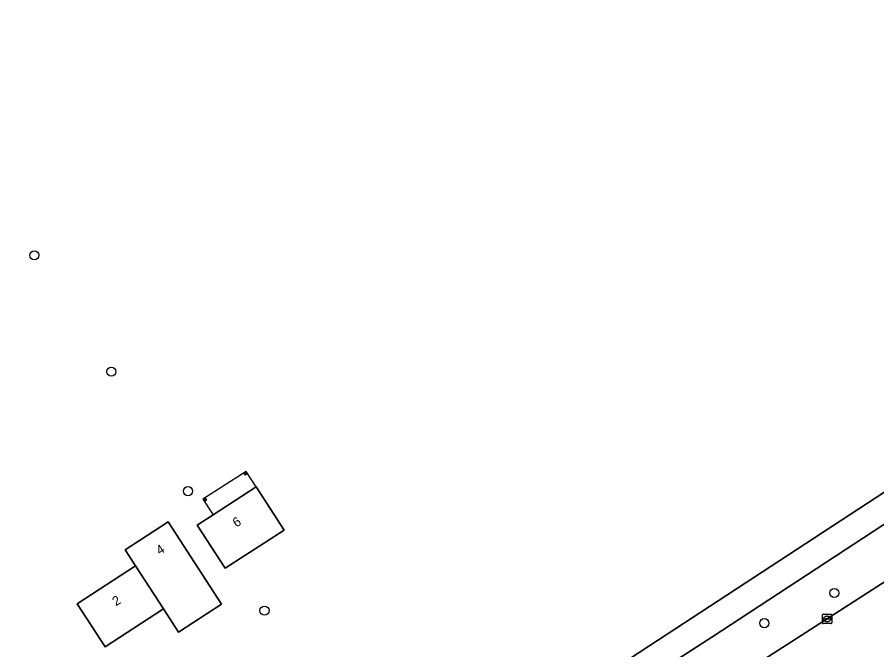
# Model space of a CAD drawing. Extents: x 159451 to 160664, y 388402 to 389723.
# Drawn here: x 159684.1 to 159776, y 389199.6 to 389267.3 of the extents above; entities that cross this region are included whole.
import ezdxf

# ---------------------------------------------------------------- set-up
doc = ezdxf.new("R2010")
doc.units = 0
for name, color, linetype in [('IMGEO_Berm_groen', 7, 'Continuous'), ('IMGEO_Boom', 7, 'Continuous'), ('IMGEO_Fietspad_gesloten', 7, 'Continuous'), ('IMGEO_Groenvoorziening', 7, 'Continuous'), ('IMGEO_Kolk', 7, 'Continuous'), ('IMGEO_Pand', 7, 'Continuous'), ('IMGEO_Pand_nummerreeks', 7, 'Continuous'), ('IMGEO_Pand_overbouw', 7, 'Continuous'), ('IMGEO_Rijbaan_lokaal_gesloten', 7, 'Continuous')]:
    doc.layers.add(name, color=color, linetype=linetype)

msp = doc.modelspace()

# ---------------------------------------------------------------- linework, layer by layer
at = {"layer": 'IMGEO_Berm_groen'}
msp.add_lwpolyline([(159781.643, 389216.263), (159758.299, 389200.996), (159737.096, 389187.355), (159738.318, 389185.435), (159741.003, 389183.824), (159754.281, 389192.419), (159786.052, 389212.871)], dxfattribs=at)
at = {"layer": 'IMGEO_Boom'}
for centre in [(159685.893, 389241.819), (159694.126, 389229.381), (159702.309, 389216.594), (159771.412, 389205.703), (159710.493, 389203.831), (159763.933, 389202.482)]:
    msp.add_circle(centre, 0.489, dxfattribs=at)
at = {"layer": 'IMGEO_Fietspad_gesloten'}
for points in [[(159683.696, 389152.464), (159687.097, 389154.672), (159691.96, 389158.015), (159702.684, 389165.018), (159709.597, 389169.401), (159714.574, 389172.778), (159719.558, 389176.127), (159726.565, 389180.529), (159731.823, 389183.917), (159737.096, 389187.355), (159758.299, 389200.996), (159781.643, 389216.263), (159789.265, 389221.193), (159827.078, 389245.82), (159832.314, 389249.122), (159833.66, 389250), (159874.622, 389276.708)], [(159858.151, 389269.353), (159792.67, 389226.891), (159787.277, 389223.364), (159784.328, 389221.435), (159717.814, 389177.926), (159716.666, 389177.127), (159711.829, 389174.024), (159709.019, 389172.233), (159708.905, 389172.147), (159708.794, 389172.235), (159699.251, 389166.039), (159696.145, 389164.01), (159691.273, 389160.827), (159687.914, 389158.632), (159677.234, 389152.002)]]:
    msp.add_lwpolyline(points, dxfattribs=at)
at = {"layer": 'IMGEO_Groenvoorziening'}
msp.add_lwpolyline([(159691.581, 389172.29), (159696.145, 389164.01), (159699.251, 389166.039), (159708.794, 389172.235), (159708.905, 389172.147), (159709.019, 389172.233), (159711.829, 389174.024), (159716.666, 389177.127), (159717.814, 389177.926), (159784.328, 389221.435), (159782.969, 389223.526), (159785.892, 389225.495), (159787.277, 389223.364), (159792.67, 389226.891), (159858.151, 389269.353)], dxfattribs=at)
for points in [[(159708.497, 389218.649), (159708.617, 389218.464), (159708.432, 389218.345), (159708.313, 389218.529)], [(159709.602, 389217.049), (159712.584, 389212.435), (159706.305, 389208.362), (159703.303, 389212.96), (159704.993, 389214.057)], [(159704.165, 389215.844), (159704.285, 389215.66), (159704.1, 389215.54), (159703.981, 389215.725)], [(159700.208, 389213.306), (159705.909, 389204.513), (159701.308, 389201.523), (159699.696, 389204.011), (159693.447, 389199.961), (159690.467, 389204.568), (159696.704, 389208.604), (159695.596, 389210.321)]]:
    msp.add_lwpolyline(points, close=True, dxfattribs=at)
at = {"layer": 'IMGEO_Kolk'}
for p, q in [((159770.133, 389202.52), (159770.133, 389203.372)), ((159770.208, 389203.446), (159771.06, 389203.446)), ((159771.134, 389203.372), (159771.134, 389202.52)), ((159771.06, 389202.446), (159770.208, 389202.446)), ((159770.392, 389202.94), (159770.392, 389202.952)), ((159770.83, 389202.903), (159770.432, 389202.903)), ((159770.435, 389202.989), (159770.833, 389202.989)), ((159770.644, 389202.666), (159770.619, 389202.666)), ((159770.621, 389203.226), (159770.646, 389203.226)), ((159770.876, 389202.952), (159770.876, 389202.94))]:
    msp.add_line(p, q, dxfattribs=at)
for points in [[(159770.133, 389202.52), (159770.133, 389203.372)], [(159770.208, 389203.446), (159771.06, 389203.446)], [(159771.134, 389203.372), (159771.134, 389202.52)], [(159771.06, 389202.446), (159770.208, 389202.446)]]:
    msp.add_lwpolyline(points, dxfattribs=at)
for centre, radius, start, end in [((159770.21, 389203.37), 0.0765, 91.55205, 178.44795), ((159770.21, 389203.37), 0.0765, 91.55205, 178.44795), ((159771.058, 389203.37), 0.0765, 1.55205, 88.44795), ((159771.058, 389203.37), 0.0765, 1.55205, 88.44795), ((159770.21, 389202.522), 0.0765, 181.55205, 268.44795), ((159770.21, 389202.522), 0.0765, 181.55205, 268.44795), ((159770.432, 389202.949), 0.0403, 85.87752, 175.75265), ((159770.429, 389202.939), 0.0366, 178.93798, 274.71019), ((159770.833, 389202.946), 0.043, 264.86636, 352.45326), ((159770.837, 389202.951), 0.0386, 1.73085, 96.63898), ((159771.058, 389202.522), 0.0765, 271.55205, 358.44795), ((159771.058, 389202.522), 0.0765, 271.55205, 358.44795)]:
    msp.add_arc(centre, radius, start, end, dxfattribs=at)
for centre, major_axis, ratio, start_param, end_param in [((159770.62, 389202.946), (-0.387, 0.002), 0.722429, 4.712389, 7.853982), ((159770.645, 389202.946), (-0.39, 0.002), 0.717154, 1.570796, 4.712389)]:
    msp.add_ellipse(centre, major_axis=major_axis, ratio=ratio, start_param=start_param, end_param=end_param, dxfattribs=at)
at = {"layer": 'IMGEO_Pand'}
for points in [[(159708.497, 389218.649), (159708.313, 389218.529), (159708.432, 389218.345), (159708.617, 389218.464)], [(159709.602, 389217.049), (159704.993, 389214.057), (159703.303, 389212.96), (159706.305, 389208.362), (159712.584, 389212.435)], [(159704.165, 389215.844), (159703.981, 389215.725), (159704.1, 389215.54), (159704.285, 389215.66)], [(159700.208, 389213.306), (159695.596, 389210.321), (159696.704, 389208.604), (159699.696, 389204.011), (159701.308, 389201.523), (159705.909, 389204.513)], [(159696.704, 389208.604), (159690.467, 389204.568), (159693.447, 389199.961), (159699.696, 389204.011)]]:
    msp.add_lwpolyline(points, close=True, dxfattribs=at)
at = {"layer": 'IMGEO_Pand_overbouw'}
msp.add_lwpolyline([(159709.602, 389217.049), (159708.523, 389218.718), (159703.915, 389215.735), (159704.993, 389214.057)], close=True, dxfattribs=at)
at = {"layer": 'IMGEO_Rijbaan_lokaal_gesloten'}
msp.add_lwpolyline([(159786.052, 389212.871), (159754.281, 389192.419), (159741.003, 389183.824), (159737.877, 389181.8), (159732.761, 389178.498), (159730.042, 389176.743), (159726.781, 389174.542), (159722.626, 389171.817), (159717.44, 389168.436), (159712.067, 389164.934), (159702.485, 389158.94), (159693.85, 389153.343), (159697.619, 389147.345), (159706.263, 389152.922), (159722.322, 389163.419), (159723.871, 389164.431), (159724.275, 389164.695), (159734.489, 389171.264), (159744.513, 389177.711), (159771.403, 389195.071), (159789.616, 389206.936)], dxfattribs=at)

# ---------------------------------------------------------------- texts
at = {"layer": 'IMGEO_Pand_nummerreeks'}
for s, rotation, p in [('6', 32.99091, (159707.485, 389212.694)), ('4', 32.9107, (159699.308, 389209.745)), ('2', 32.90497, (159694.624, 389204.28))]:
    msp.add_text(s, height=1, rotation=rotation, dxfattribs=at).set_placement(p)

doc.saveas('drawing.dxf')
